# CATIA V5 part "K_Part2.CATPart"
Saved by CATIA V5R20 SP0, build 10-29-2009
Part number: barres_intermediaire_poigne
Publications: "Corps principal", "hauteur des barres", "ecart entre les barres", "Point.1", "Point.2", "Point.3", "Point.4", "Droite.1", "Droite.2", "Droite.3", "Droite.4"
Bounding box of the stored display mesh (mm): x -50 to 50, y -100 to 100, z 0 to 1000
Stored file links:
  G:\Khaled_CFAO_2011\ST2M\ST2M_GR1\cdurantin\cdurantin\Khaled\CAD_ThinkMOTION\K_Part2.CATPart
  G:\Khaled_CFAO_2011\ST2M\ST2M_GR1\cdurantin\cdurantin\Khaled\CAD_ThinkMOTION\K_Corps.CATPart
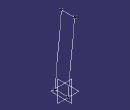
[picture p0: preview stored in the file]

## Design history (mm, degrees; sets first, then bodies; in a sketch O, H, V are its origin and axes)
Parameters
  `hauteur des barres` = 1000 mm
  `ecart entre les barres` = 200 mm
External parameters (linked from other documents)
  `External.Ecart entre les barres du corps` = 100 mm
Body1 (main body)
  Point1: type OnPlane, Support xy-plane, H 50 {= `External.Ecart entre les barres du corps` /2}, V 100 {= `ecart entre les barres` /2}, Direction (1, 0, 0)
  Point2: type OnPlane, Support xy-plane, H 50 {= `External.Ecart entre les barres du corps` /2}, V -100 {= -`ecart entre les barres` /2}, Direction (1, 0, 0)
  Point3: (-50 {= -`External.Ecart entre les barres du corps` /2}, 100 {= `ecart entre les barres` /2}, 1000 {= `hauteur des barres`})
  Point4: (-50 {= -`External.Ecart entre les barres du corps` /2}, -100 {= -`ecart entre les barres` /2}, 1000 {= `hauteur des barres`})
  Line1: type PtPt, FirstPoint Point1, SecondPoint Point2
  Line2: type PtPt, FirstPoint Point1, SecondPoint Point3
  Line3: type PtPt, FirstPoint Point4, SecondPoint Point2
  Line4: type PtPt, FirstPoint Point3, SecondPoint Point4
